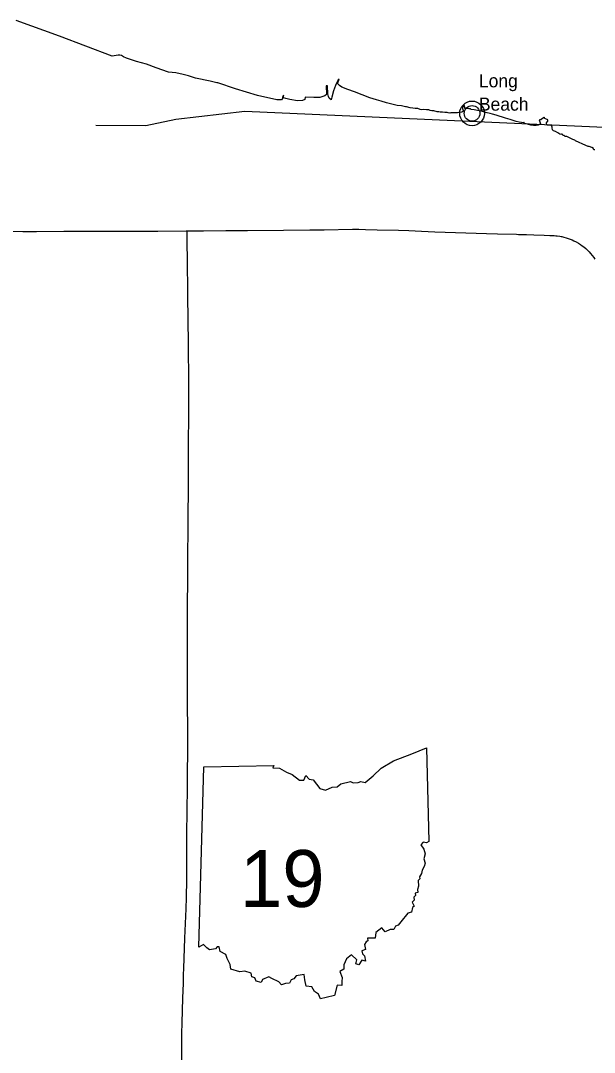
# Model space of a CAD drawing. Extents: x -82 to 873, y 0 to 440.
# Drawn here: x 264.9 to 310.6, y 192.1 to 274.2 of the extents above; entities that cross this region are included whole.
import ezdxf

# ---------------------------------------------------------------- set-up
doc = ezdxf.new("R2010")
doc.units = 0
for name, color, linetype in [('DV_X_Corp_Line', 7, 'Continuous'), ('DV_X_County_Line', 7, 'Continuous'), ('GM_X_County', 7, 'Continuous'), ('GM_X_Interstate_Route', 7, 'Continuous'), ('PV_P_Text', 7, 'Continuous')]:
    doc.layers.add(name, color=color, linetype=linetype)

msp = doc.modelspace()

# ---------------------------------------------------------------- linework, layer by layer
at = {"layer": 'DV_X_Corp_Line'}
for radius in [0.982, 0.623]:
    msp.add_circle((300.85, 266.841), radius, dxfattribs=at)
at = {"layer": 'DV_X_County_Line'}
for p, q in [((277.257, 266.381), (282.754, 267.019)), ((282.754, 267.019), (311.973, 265.73)), ((274.876, 265.871), (277.257, 266.381)), ((270.878, 265.91), (274.876, 265.871))]:
    msp.add_line(p, q, dxfattribs=at)
at = {"layer": 'GM_X_County'}
for points in [[(268.007, 272.996), (264.543, 274.225)], [(310.62, 263.939), (310.572, 263.947), (310.546, 263.958), (310.531, 263.986), (310.511, 264.041), (310.381, 264.119), (310.186, 264.208), (310.105, 264.201), (309.912, 264.283), (309.083, 264.661), (309.034, 264.707), (308.883, 264.759), (308.406, 264.993), (308.345, 264.997), (308.276, 265.017), (308.189, 265.073), (308.104, 265.091), (308.072, 265.119), (308.064, 265.176), (308.024, 265.195), (307.976, 265.184), (307.918, 265.175), (307.844, 265.201), (307.679, 265.288), (307.49, 265.392), (307.334, 265.449), (307.254, 265.524), (307.249, 265.566), (307.228, 265.672), (307.228, 265.757), (307.214, 265.818), (307.193, 265.842), (307.147, 265.876), (307.067, 265.9), (306.991, 265.9), (306.904, 265.907), (306.859, 265.913), (306.811, 265.967), (306.776, 266.024), (306.774, 266.046), (306.778, 266.1), (306.824, 266.165), (306.876, 266.215), (306.887, 266.254), (306.887, 266.317), (306.876, 266.341), (306.648, 266.449), (306.618, 266.497), (306.615, 266.527), (306.589, 266.536), (306.533, 266.497), (306.364, 266.36), (306.325, 266.336), (306.29, 266.336), (306.242, 266.336), (306.223, 266.315), (306.205, 266.293), (306.287, 266.027), (306.215, 265.964), (306.113, 265.903), (305.968, 265.869), (305.746, 265.877), (305.525, 265.918), (305.349, 265.957), (305.16, 266.01), (305.052, 266.041), (305.01, 266.055), (304.999, 266.071), (304.998, 266.12), (304.974, 266.114), (304.937, 266.085), (304.785, 266.116), (304.607, 266.157), (304.364, 266.207), (303.885, 266.349), (303.5, 266.451), (302.773, 266.702), (302.489, 266.782), (302.302, 266.825), (302.061, 266.897), (301.76, 266.979), (301.569, 267.018), (301.274, 267.07), (301.007, 267.12), (300.777, 267.159), (300.714, 267.194), (300.657, 267.205), (300.614, 267.205), (300.551, 267.222), (300.516, 267.235), (300.462, 267.229), (300.403, 267.227), (300.345, 267.216), (300.301, 267.216), (300.23, 267.485), (300.189, 267.476), (300.089, 267.326), (300.082, 267.229), (300.156, 267.023), (300.102, 266.994), (300.03, 266.947), (299.896, 266.908), (299.804, 266.903), (299.696, 266.884), (299.553, 266.881), (299.275, 266.89), (299.216, 266.892), (299.171, 266.893), (299.069, 266.873), (298.96, 266.884), (298.865, 266.907), (298.669, 266.927), (298.494, 266.931), (298.298, 266.949), (298.214, 266.966), (298.083, 266.972), (297.817, 267.046), (297.658, 267.051), (297.511, 267.083), (297.406, 267.131), (297.224, 267.116), (296.983, 267.155), (296.855, 267.139), (296.714, 267.161), (296.521, 267.231), (296.315, 267.233), (296.139, 267.257), (295.929, 267.291), (295.642, 267.355), (295.538, 267.365), (295.243, 267.437), (294.877, 267.478), (294.574, 267.56), (294.036, 267.682), (293.6, 267.825), (293.233, 267.916), (292.721, 268.079), (291.48, 268.554), (290.95, 268.754), (290.49, 268.927), (290.282, 269.057), (290.169, 269.192), (290.165, 269.283), (290.26, 269.578), (290.186, 269.513), (289.987, 269.053), (289.822, 268.637), (289.67, 268.146), (289.631, 267.929), (289.483, 268.05), (289.405, 268.198), (289.353, 268.389), (289.336, 269.049), (289.231, 269.049), (289.266, 268.354), (289.136, 268.241), (288.719, 268.12), (288.372, 268.102), (288.242, 268.102), (287.565, 268.128), (287.521, 267.937), (287.348, 267.876), (286.94, 267.85), (286.341, 267.937), (286.011, 268.015), (285.846, 268.093), (285.837, 268.293), (285.751, 268.119), (285.759, 268.024), (285.681, 267.928), (285.464, 267.911), (285.299, 267.911), (283.763, 268.258), (282.018, 268.787), (280.594, 269.273), (280.538, 269.286), (279.987, 269.404), (278.832, 269.647), (278.276, 269.82), (277.842, 269.942), (277.261, 270.072), (276.688, 270.124), (275.707, 270.471), (274.934, 270.766), (274.127, 270.974), (273.32, 271.226), (273.094, 271.339), (272.938, 271.443), (272.808, 271.486), (272.666, 271.474), (272.183, 271.408), (268.007, 272.996)]]:
    msp.add_lwpolyline(points, dxfattribs=at)
at = {"layer": 'GM_X_Interstate_Route'}
for points in [[(255.216, 257.559), (256.203, 257.547), (257.435, 257.538), (258.357, 257.526), (258.542, 257.524), (259.199, 257.516), (260.389, 257.503), (264.165, 257.46), (265.07, 257.451), (265.191, 257.449), (266.176, 257.454), (268.341, 257.46), (268.761, 257.461), (270.731, 257.463), (271.265, 257.466), (272.455, 257.469), (274.015, 257.477), (275.246, 257.477), (275.822, 257.479)], [(275.822, 257.479), (278.078, 257.487), (278.161, 257.487)], [(278.161, 257.487), (278.858, 257.493), (279.473, 257.5), (281.234, 257.514)], [(278.252, 235.619), (278.259, 236.116), (278.264, 236.896), (278.265, 237.429), (278.259, 238.537), (278.26, 239.234), (278.261, 240.096), (278.264, 240.361), (278.271, 241.039), (278.283, 242.311), (278.289, 243.255), (278.296, 244.486), (278.295, 245.552), (278.294, 246.045), (278.288, 246.619), (278.285, 246.81), (278.281, 247.07), (278.268, 247.85), (278.259, 248.629), (278.239, 250.311), (278.215, 252.444), (278.208, 253.265), (278.193, 254.454), (278.188, 255.111), (278.175, 256.629), (278.164, 257.326), (278.161, 257.487)], [(281.234, 257.514), (282.346, 257.524), (282.737, 257.526), (282.961, 257.527), (285.834, 257.551), (287.927, 257.568), (289.076, 257.576), (291.333, 257.616), (291.825, 257.618), (292.359, 257.609), (293.302, 257.579), (294.984, 257.54), (295.817, 257.511)], [(295.817, 257.511), (296.83, 257.476), (297.896, 257.429), (301.998, 257.297), (302.872, 257.265), (304.396, 257.222), (304.549, 257.217)], [(304.549, 257.217), (305.179, 257.196), (305.757, 257.178), (306.581, 257.153), (307.045, 257.132), (307.184, 257.125), (307.389, 257.114), (307.525, 257.103), (307.634, 257.091), (307.837, 257.063), (307.838, 257.063), (307.94, 257.045), (307.998, 257.034), (308.157, 256.999), (308.355, 256.945), (308.511, 256.896), (308.665, 256.841), (308.817, 256.78), (308.965, 256.711), (309.147, 256.617), (309.325, 256.515), (309.497, 256.406), (309.631, 256.312), (309.761, 256.212), (309.918, 256.081), (310.069, 255.943), (310.183, 255.826), (310.292, 255.703), (310.421, 255.544), (310.542, 255.38), (310.634, 255.244)], [(278.221, 230.474), (278.221, 230.58), (278.222, 230.947), (278.226, 231.481), (278.241, 233.901), (278.247, 235.183), (278.248, 235.296), (278.252, 235.619)], [(277.733, 191.529), (277.742, 192.637), (277.751, 193.58), (277.769, 194.483), (277.795, 195.426), (277.822, 196.451), (277.858, 197.585), (277.881, 198.296), (277.901, 198.788), (277.989, 201.207), (278.076, 203.544), (278.111, 204.446), (278.122, 204.856), (278.123, 205.43), (278.123, 206.005), (278.129, 207.276), (278.145, 209.984), (278.152, 210.82), (278.157, 211.42), (278.176, 213.102), (278.186, 214.62), (278.206, 215.768), (278.211, 216.384), (278.215, 217.081), (278.21, 218.066), (278.189, 219.584), (278.185, 220.322), (278.186, 220.896), (278.186, 221.922), (278.188, 222.701), (278.191, 223.645), (278.193, 224.051), (278.193, 224.712), (278.191, 225.569), (278.197, 226.517), (278.195, 226.967), (278.199, 227.378), (278.199, 227.824), (278.217, 229.552), (278.221, 230.373), (278.221, 230.474)]]:
    msp.add_lwpolyline(points, dxfattribs=at)
at = {"layer": 'PV_P_Text'}
msp.add_line((279.094, 200.482), (279.494, 214.845), dxfattribs=at)
msp.add_line((279.094, 200.482), (279.494, 214.845), dxfattribs=at)
for points in [[(279.494, 214.845), (285.067, 214.939), (284.98, 214.765), (285.506, 214.729), (286.064, 214.422), (286.537, 214.229), (287.115, 213.772), (287.46, 213.777), (287.606, 214.151), (287.871, 213.862), (288.185, 213.811), (288.729, 213.123), (289.177, 212.975), (289.714, 213.21), (290.116, 213.249), (290.409, 213.482), (291.174, 213.681), (291.387, 213.562), (291.792, 213.586), (291.996, 213.674), (292.349, 213.595), (292.97, 214.118), (293.61, 214.734), (294.594, 215.315), (296.064, 215.865), (297.227, 216.358), (297.395, 208.904)], [(279.494, 214.845), (285.067, 214.939), (284.98, 214.765), (285.506, 214.729), (286.064, 214.422), (286.537, 214.229), (287.115, 213.772), (287.46, 213.777), (287.606, 214.151), (287.871, 213.862), (288.185, 213.811), (288.729, 213.123), (289.177, 212.975), (289.714, 213.21), (290.116, 213.249), (290.409, 213.482), (291.174, 213.681), (291.387, 213.562), (291.792, 213.586), (291.996, 213.674), (292.349, 213.595), (292.97, 214.118), (293.61, 214.734), (294.594, 215.315), (296.064, 215.865), (297.227, 216.358), (297.395, 208.904)], [(297.395, 208.904), (297.224, 208.8), (296.957, 208.849), (296.777, 208.64), (296.999, 208.291), (297.104, 207.923), (297.011, 207.516), (297.103, 207.181), (297.041, 206.901), (296.873, 206.622), (296.815, 206.356), (296.673, 206.076), (296.684, 205.919), (296.548, 205.794), (296.573, 205.328), (296.504, 205.07), (296.528, 204.847), (296.307, 204.789), (296.358, 204.605), (296.217, 204.462), (296.248, 204.218), (296.088, 204.062), (296.243, 203.749), (296.119, 203.65), (296.016, 203.269), (295.733, 203.192), (295.166, 202.496), (294.966, 202.234), (294.742, 202.168), (294.618, 201.898), (294.341, 201.897), (293.923, 201.71), (293.652, 202.032), (293.178, 201.644), (293.123, 201.196), (292.524, 201.211), (292.547, 200.984), (292.413, 200.918), (292.292, 200.691), (292.362, 200.288), (292.082, 200.186), (292.116, 199.951), (292.296, 199.808), (292.375, 199.361), (292.077, 199.452), (291.833, 199.075), (291.582, 199.163), (291.664, 199.482), (291.239, 199.866), (290.838, 199.559), (290.628, 199.067), (290.626, 198.737), (290.327, 198.537), (290.519, 198.07), (290.484, 197.748), (290.489, 197.443), (290.115, 197.453), (289.889, 196.629)], [(297.395, 208.904), (297.224, 208.8), (296.957, 208.849), (296.777, 208.64), (296.999, 208.291), (297.104, 207.923), (297.011, 207.516), (297.103, 207.181), (297.041, 206.901), (296.873, 206.622), (296.815, 206.356), (296.673, 206.076), (296.684, 205.919), (296.548, 205.794), (296.573, 205.328), (296.504, 205.07), (296.528, 204.847), (296.307, 204.789), (296.358, 204.605), (296.217, 204.462), (296.248, 204.218), (296.088, 204.062), (296.243, 203.749), (296.119, 203.65), (296.016, 203.269), (295.733, 203.192), (295.166, 202.496), (294.966, 202.234), (294.742, 202.168), (294.618, 201.898), (294.341, 201.897), (293.923, 201.71), (293.652, 202.032), (293.178, 201.644), (293.123, 201.196), (292.524, 201.211), (292.547, 200.984), (292.413, 200.918), (292.292, 200.691), (292.362, 200.288), (292.082, 200.186), (292.116, 199.951), (292.296, 199.808), (292.375, 199.361), (292.077, 199.452), (291.833, 199.075), (291.582, 199.163), (291.664, 199.482), (291.239, 199.866), (290.838, 199.559), (290.628, 199.067), (290.626, 198.737), (290.327, 198.537), (290.519, 198.07), (290.484, 197.748), (290.489, 197.443), (290.115, 197.453), (289.889, 196.629)], [(289.889, 196.629), (289.238, 196.471), (288.787, 196.377), (288.628, 196.751), (288.305, 196.949), (288.095, 197.326), (287.631, 197.377), (287.521, 197.895), (287.47, 198.315), (286.836, 198.211), (286.662, 197.954), (286.437, 197.885), (286.307, 197.627), (286, 197.605), (285.671, 197.483), (285.456, 197.737), (284.917, 197.992), (284.675, 198.123), (284.169, 197.919), (284.061, 197.677), (283.658, 197.783), (283.563, 198.053), (283.319, 198.134), (283.265, 198.42), (282.744, 198.572), (282.345, 198.512), (281.641, 198.742), (281.599, 199.118), (281.359, 199.577), (281.234, 199.895), (280.789, 200.139), (280.699, 200.517), (280.557, 200.506), (280.427, 200.352), (279.933, 200.282), (279.735, 200.437), (279.459, 200.701), (279.094, 200.482)], [(289.889, 196.629), (289.238, 196.471), (288.787, 196.377), (288.628, 196.751), (288.305, 196.949), (288.095, 197.326), (287.631, 197.377), (287.521, 197.895), (287.47, 198.315), (286.836, 198.211), (286.662, 197.954), (286.437, 197.885), (286.307, 197.627), (286, 197.605), (285.671, 197.483), (285.456, 197.737), (284.917, 197.992), (284.675, 198.123), (284.169, 197.919), (284.061, 197.677), (283.658, 197.783), (283.563, 198.053), (283.319, 198.134), (283.265, 198.42), (282.744, 198.572), (282.345, 198.512), (281.641, 198.742), (281.599, 199.118), (281.359, 199.577), (281.234, 199.895), (280.789, 200.139), (280.699, 200.517), (280.557, 200.506), (280.427, 200.352), (279.933, 200.282), (279.735, 200.437), (279.459, 200.701), (279.094, 200.482)]]:
    msp.add_lwpolyline(points, dxfattribs=at)

# ---------------------------------------------------------------- texts
at = {"layer": 'DV_X_Corp_Line'}
for s, p in [('Long', (301.395, 268.918)), ('Beach', (301.395, 267.059))]:
    msp.add_text(s, height=1.0417, rotation=0.00501, dxfattribs=at).set_placement(p)
at = {"layer": 'PV_P_Text'}
msp.add_text('19', height=4.5281, rotation=0.005, dxfattribs=at).set_placement((282.367, 203.685))

doc.saveas('drawing.dxf')
